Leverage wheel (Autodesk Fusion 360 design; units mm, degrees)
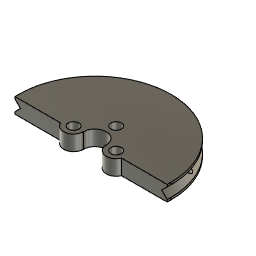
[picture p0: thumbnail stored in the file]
sketch "Sketch1" plane through (0, 0, 0) normal (0, 0, 1) x axis (1, 0, 0)
  line L1 (11.5, 12.5) -> (4.5, 12.5)
  line L2 (36.5, 12.5) -> (-13.5, 12.5)
  circle C1 centre (11.5, 19.5) radius 1.75
  circle C2 centre (18.5, 12.5) radius 1.75
  circle C3 centre (11.5, 5.5) radius 1.75
  circle C4 centre (11.5, 12.5) radius 3.75
  circle C5 centre (4.5, 12.5) radius 1.75
  circle C6 centre (11.5, 12.5) radius 25
  circle C7 centre (4.5, 12.5) radius 3.25
  circle C8 centre (18.5, 12.5) radius 3.25
  point P4 (4.5, 12.5)
  point P3 (4.5, 12.5)
  point P5 (11.5, 12.5)
  point P6 (11.5, 12.5)
  point P10 (-13.5, 12.5)
  point P11 (36.5, 12.5)
  coincident P4 L2
  coincident P3 P4
  parallel L1 L2
  coincident P5 P6
  concentric C4 C6
  coincident C6 P10
  coincident C6 P11
  concentric C5 C7
  tangent C4 C7
  concentric C2 C8
  tangent C4 C8
  dimension "d4" diameter C5 = 3.5
  dimension "d5" distance P3 P6 = 7
  dimension "d6" diameter C4 = 7.5
  dimension "d9" diameter C6 = 50
  dimension "d2" C-Pattern1-Angle = 360
extrude "Extrude1" new body sketch "Sketch1" profile of C1 C2 L1 L2 C4 C5 C6 C7 C8 along normal blind 5
sketch "Sketch4" plane through (0, 0, 5) normal (0, 0, 1) x axis (-1, 0, 0)
  line L1 (-36.5, -12.5) -> (-21.75, -12.5)
  line L2 (-1.25, -12.5) -> (13.5, -12.5)
  line L3 (13.5, -12.5) -> (-11.5, -12.5)
  line L4 (13.5, -13.75) -> (13.5, -12.5)
  line L5 (-11.5, -13.75) -> (13.5, -13.75)
  line L6 (-11.5, -12.5) -> (-11.5, -13.75)
  line L7 (-11.5, -11.25) -> (13.5, -11.25)
  line L8 (-1.25, -12.5) -> (13.5, -12.5)
  line L9 (13.5, -12.5) -> (-11.5, -12.5)
  line L10 (-11.5, -12.5) -> (-11.5, -11.25)
  line L11 (13.5, -11.25) -> (13.5, -12.5)
  line L12 (6.1777, 5.1777) -> (-11.5, -12.5)
  line L13 (-12.3839, -11.6161) -> (5.2938, 6.0616)
  line L14 (5.2938, 6.0616) -> (6.1777, 5.1777)
  line L15 (6.1777, 5.1777) -> (-11.5, -12.5)
  line L16 (-11.5, -12.5) -> (-10.6161, -13.3839)
  line L17 (-4.2522, -5.2522) -> (6.1777, 5.1777)
  line L18 (-10.6161, -13.3839) -> (7.0616, 4.2938)
  line L19 (7.0616, 4.2938) -> (6.1777, 5.1777)
  line L20 (-4.2522, -5.2522) -> (6.1777, 5.1777)
  line L21 (-11.5, -12.5) -> (-12.3839, -11.6161)
  line L22 (-11.5, 12.5) -> (-11.5, -12.5)
  line L23 (-12.75, -12.5) -> (-12.75, 12.5)
  line L24 (-12.75, 12.5) -> (-11.5, 12.5)
  line L25 (-11.5, 12.5) -> (-11.5, -12.5)
  line L26 (-11.5, -12.5) -> (-10.25, -12.5)
  line L27 (-11.5, -2.25) -> (-11.5, 12.5)
  line L28 (-10.25, -12.5) -> (-10.25, 12.5)
  line L29 (-10.25, 12.5) -> (-11.5, 12.5)
  line L30 (-11.5, -2.25) -> (-11.5, 12.5)
  line L31 (-11.5, -12.5) -> (-12.75, -12.5)
  line L32 (-29.1777, 5.1777) -> (-11.5, -12.5)
  line L33 (-12.3839, -13.3839) -> (-30.0616, 4.2938)
  line L34 (-30.0616, 4.2938) -> (-29.1777, 5.1777)
  line L35 (-29.1777, 5.1777) -> (-11.5, -12.5)
  line L36 (-11.5, -12.5) -> (-10.6161, -11.6161)
  line L37 (-18.7478, -5.2522) -> (-29.1777, 5.1777)
  line L38 (-10.6161, -11.6161) -> (-28.2938, 6.0616)
  line L39 (-28.2938, 6.0616) -> (-29.1777, 5.1777)
  line L40 (-18.7478, -5.2522) -> (-29.1777, 5.1777)
  line L41 (-11.5, -12.5) -> (-12.3839, -13.3839)
  line L42 (-36.5, -12.5) -> (-11.5, -12.5)
  line L43 (-11.5, -13.75) -> (-36.5, -13.75)
  line L44 (-36.5, -13.75) -> (-36.5, -12.5)
  line L45 (-36.5, -12.5) -> (-11.5, -12.5)
  line L46 (-11.5, -12.5) -> (-11.5, -11.25)
  line L47 (-21.75, -12.5) -> (-36.5, -12.5)
  line L48 (-11.5, -11.25) -> (-36.5, -11.25)
  line L49 (-36.5, -11.25) -> (-36.5, -12.5)
  line L50 (-21.75, -12.5) -> (-36.5, -12.5)
  line L51 (-11.5, -12.5) -> (-11.5, -13.75)
  line L52 (-29.1777, -30.1777) -> (-11.5, -12.5)
  line L53 (-10.6161, -13.3839) -> (-28.2938, -31.0616)
  line L54 (-28.2938, -31.0616) -> (-29.1777, -30.1777)
  line L55 (-29.1777, -30.1777) -> (-11.5, -12.5)
  line L56 (-11.5, -12.5) -> (-12.3839, -11.6161)
  line L57 (-18.7478, -19.7478) -> (-29.1777, -30.1777)
  line L58 (-12.3839, -11.6161) -> (-30.0616, -29.2938)
  line L59 (-30.0616, -29.2938) -> (-29.1777, -30.1777)
  line L60 (-18.7478, -19.7478) -> (-29.1777, -30.1777)
  line L61 (-11.5, -12.5) -> (-10.6161, -13.3839)
  line L62 (-11.5, -37.5) -> (-11.5, -12.5)
  line L63 (-10.25, -12.5) -> (-10.25, -37.5)
  line L64 (-10.25, -37.5) -> (-11.5, -37.5)
  line L65 (-11.5, -37.5) -> (-11.5, -12.5)
  line L66 (-11.5, -12.5) -> (-12.75, -12.5)
  line L67 (-11.5, -22.75) -> (-11.5, -37.5)
  line L68 (-12.75, -12.5) -> (-12.75, -37.5)
  line L69 (-12.75, -37.5) -> (-11.5, -37.5)
  line L70 (-11.5, -22.75) -> (-11.5, -37.5)
  line L71 (-11.5, -12.5) -> (-10.25, -12.5)
  line L72 (6.1777, -30.1777) -> (-11.5, -12.5)
  line L73 (-10.6161, -11.6161) -> (7.0616, -29.2938)
  line L74 (7.0616, -29.2938) -> (6.1777, -30.1777)
  line L75 (6.1777, -30.1777) -> (-11.5, -12.5)
  line L76 (-11.5, -12.5) -> (-12.3839, -13.3839)
  line L77 (-4.2522, -19.7478) -> (6.1777, -30.1777)
  line L78 (-12.3839, -13.3839) -> (5.2938, -31.0616)
  line L79 (5.2938, -31.0616) -> (6.1777, -30.1777)
  line L80 (-4.2522, -19.7478) -> (6.1777, -30.1777)
  line L81 (-11.5, -12.5) -> (-10.6161, -11.6161)
  circle C1 centre (-18.5, -12.5) radius 1.75
  circle C2 centre (-11.5, -19.5) radius 1.75
  circle C3 centre (-4.5, -12.5) radius 1.75
  arc A1 centre (-18.5, -12.5) radius 3.25 clockwise from (-21.75, -12.5) to (-15.25, -12.5)
  arc A2 centre (-11.5, -12.5) radius 25 clockwise from (13.5, -12.5) to (-36.5, -12.5)
  arc A3 centre (-4.5, -12.5) radius 3.25 clockwise from (-7.75, -12.5) to (-1.25, -12.5)
  arc A4 centre (-11.5, -12.5) radius 3.75 clockwise from (-7.75, -12.5) to (-15.25, -12.5)
  circle C4 centre (-11.5, -12.5) radius 22.5
  circle C5 centre (-4.5, -12.5) radius 3.25
  circle C6 centre (-11.5, -19.5) radius 3.25
  circle C7 centre (-18.5, -12.5) radius 3.25
  circle C8 centre (-11.5, -12.5) radius 6.25
  point P6 (-21.75, -12.5)
  point P9 (-11.5, -12.5)
  point P16 (-11.5, -12.5)
  point P4 (-4.5, -12.5)
  point P26 (-4.5, -12.5)
  point P8 (13.5, -12.5)
  point P22 (13.5, -12.5)
  point P23 (-11.5, -12.5)
  point P10 (-1.25, -12.5)
  point P27 (-1.25, -12.5)
  point P11 (-7.75, -12.5)
  point P24 (-7.75, -12.5)
  point P12 (-11.5, -12.5)
  point P20 (-11.5, -12.5)
  point P13 (-4.5, -12.5)
  point P28 (-4.5, -12.5)
  point P21 (-11.5, -12.5)
  point P17 (13.5, -12.5)
  point P25 (13.5, -12.5)
  point P18 (13.5, -13.75)
  point P29 (13.5, -11.25)
  point P19 (-11.5, -13.75)
  point P30 (-11.5, -11.25)
  point P44 (-11.5, -12.5)
  point P185 (-11.5, -12.5)
  concentric A2 C4
  concentric C3 C5
  concentric C2 C6
  tangent A4 C6
  concentric C1 C7
  coincident P6 C7
  horizontal L3
  vertical L4
  horizontal L5
  vertical L6
  coincident P9 P16
  symmetric P4 L3 P26
  symmetric P8 L3 P22
  symmetric P9 L3 P23
  symmetric P10 L3 P27
  symmetric P11 L3 P24
  symmetric P12 L3 P20
  symmetric P13 L3 P28
  symmetric P16 L3 P21
  symmetric P17 L3 P25
  symmetric P18 L3 P29
  symmetric P19 L3 P30
  coincident P44 P185
  dimension "d23" diameter C4 = 45
  dimension "d24" distance P16 P17 = 25
  dimension "d25" distance P16 P19 = 1.25
  dimension "d28" diameter C8 = 12.5
  dimension "d27" C-Pattern1-Angle = 360
sketch "Sketch5" plane through (0, 0, 5) normal (0, 0, 1) x axis (-1, 0, 0)
  line L1 (-36.5, -12.5) -> (-21.75, -12.5)
  line L2 (-1.25, -12.5) -> (13.5, -12.5)
  line L3 (-36.5, -11.25) -> (-36.5, -12.5)
  line L4 (-11.5, -11.25) -> (-36.5, -11.25)
  line L5 (13.5, -11.25) -> (13.5, -12.5)
  line L6 (-11.5, -11.25) -> (13.5, -11.25)
  circle C1 centre (-18.5, -12.5) radius 1.75
  circle C2 centre (-11.5, -19.5) radius 1.75
  circle C3 centre (-4.5, -12.5) radius 1.75
  arc A1 centre (-18.5, -12.5) radius 3.25 clockwise from (-21.75, -12.5) to (-15.25, -12.5)
  arc A2 centre (-11.5, -12.5) radius 25 clockwise from (13.5, -12.5) to (-36.5, -12.5)
  arc A3 centre (-4.5, -12.5) radius 3.25 clockwise from (-7.75, -12.5) to (-1.25, -12.5)
  arc A4 centre (-11.5, -12.5) radius 3.75 clockwise from (-7.75, -12.5) to (-15.25, -12.5)
extrude "Extrude5" add sketch "Sketch4" + "Sketch5" profile of S1:A1 S1:L1 S1:C4 S1:C7 S1:L42 S1:L45 S1:L47 S1:L48 S1:L50 S2:A1 S2:L1 S2:L2 S2:A3 S2:L3 S2:L4 S2:L5 S2:L6 to an object
move "Move1"
work_plane "WorkPlane1" AlongDistance -25
sketch "Sketch7" plane through (-25, 0, 0) normal (1, 0, 0) x axis (0, 1, 0)
  line L1 (-1.25, 0) -> (0, 0)
  line L2 (-1.25, 5) -> (-1.25, 0)
  line L3 (0, 5) -> (-1.25, 5)
  line L4 (0, 0) -> (0, 5)
  line L5 (0, 0) -> (25, 0)
  line L6 (0, 5) -> (0, 0)
  line L7 (0, 5) -> (25, 5)
  line L8 (0, 0) -> (0, 5)
  line L9 (3, 2.5) -> (-1.25, 2.5)
  circle C1 centre (0.95, 2.5) radius 1.1
  point P10 (-1.25, 2.5)
  point P12 (0.95, 2.5)
  midpoint L2 P10
  perpendicular L2 L9
  coincident L9 P12
  dimension "d39" diameter C1 = 2.2
  dimension "d40" distance L2 P12 = 2.2 (= "d39")
extrude "Extrude7" cut sketch "Sketch7" profile of C1 along normal blind 6
circular_pattern "C-Pattern2" TotalAngle 360
sketch "Sketch9" plane through (0, 0, 0) normal (0, 1, 0) x axis (1, 0, 0)
  line L1 (25, 0) -> (10, 0)
  line L2 (25, -5) -> (25, 0)
  line L3 (10, -5) -> (25, -5)
  line L4 (10, 0) -> (10, -5)
  line L5 (20.5, -2.5) -> (25, -2.5)
  line L6 (22.5, -2.5) -> (25, -5)
  line L7 (28.5355, -5) -> (25, -5)
  line L8 (25, 0) -> (22.5, -2.5)
  line L9 (23.2071, -2.5) -> (25.7071, -5)
  line L10 (25.7071, 0) -> (23.2071, -2.5)
  line L11 (24.5, -3.7929) -> (24.5, -1.2071)
  line L12 (25.7071, 0) -> (25.7071, -5)
  point P6 (25, -2.5)
  point P4 (25, -5)
  point P8 (25, -5)
  point P9 (22.5, -2.5)
  point P11 (24.5, -3.7929)
  point P13 (24.5, -1.2071)
  midpoint L2 P6
  perpendicular L2 L5
  horizontal L7
  coincident P4 P8
  coincident L5 P9
  perpendicular L6 L8
  coincident P8 L6
  coincident P11 L9
  coincident P13 L10
  dimension "d48" angle L6 L7 = 135
revolve "Revolve2" sketch "Sketch9" AlongAngle 360
sketch "Sketch8" plane through (0, -1.25, 0) normal (0, -1, 0) x axis (1, 0, 0)
  line L1 (-10, 0) -> (-25, 0)
  line L2 (-10, 5) -> (-10, 0)
  line L3 (-25, 5) -> (-10, 5)
  line L4 (-25, 0) -> (-25, 5)
  line L5 (-19.3392, 2.5) -> (-25, 2.5)
  line L6 (-22.5, 2.5) -> (-25, 5)
  line L7 (-21.4645, 5) -> (-25, 5)
  line L8 (-25, 0) -> (-22.5, 2.5)
  line L9 (-25, 5) -> (-25, 0)
  line L10 (-23.5607, 2.5) -> (-25.5303, 4.4697)
  line L11 (-25.5303, 0.5303) -> (-23.5607, 2.5)
  line L12 (-25.5303, 0.5303) -> (-25.5303, 4.4697)
  point P6 (-25, 2.5)
  point P5 (-25, 5)
  point P8 (-25, 5)
  point P9 (-22.5, 2.5)
  point P2 (-25, 0)
  point P11 (-25, 0)
  point P12 (-25, 0)
  point P13 (-25, 5)
  midpoint L4 P6
  perpendicular L4 L5
  horizontal L7
  coincident P5 P8
  coincident L5 P9
  coincident P2 P11
  coincident P2 P12
  coincident P5 P13
  dimension "d45" angle L6 L7 = 45
  dimension "d46" = 0.75
revolve "Revolve1" sketch "Sketch8" AlongAngle 360
extrude "Extrude6" cut sketch "Sketch7" along normal blind 2
circular_pattern "C-Pattern1" TotalAngle 360
sketch "Sketch2" plane through (0, 0, 2.5) normal (0, 0, 1) x axis (-1, 0, 0)
  line L1 (-36.5, -12.5) -> (-21.75, -12.5)
  line L2 (-1.25, -12.5) -> (13.5, -12.5)
  line L3 (18.5, -12.5) -> (-11.5, -12.5)
  line L4 (18.5, -15) -> (18.5, -12.5)
  line L5 (-11.5, -15) -> (18.5, -15)
  line L6 (-11.5, -12.5) -> (-11.5, -15)
  line L7 (-11.5, -12.5) -> (-9.7322, -14.2678)
  line L8 (-4.2522, -5.2522) -> (6.1777, 5.1777)
  line L9 (-9.7322, -14.2678) -> (11.481, 6.9454)
  line L10 (11.481, 6.9454) -> (9.7132, 8.7132)
  line L11 (9.7132, 8.7132) -> (-11.5, -12.5)
  line L12 (-11.5, -12.5) -> (-9, -12.5)
  line L13 (-11.5, -2.25) -> (-11.5, 12.5)
  line L14 (-9, -12.5) -> (-9, 17.5)
  line L15 (-9, 17.5) -> (-11.5, 17.5)
  line L16 (-11.5, 17.5) -> (-11.5, -12.5)
  line L17 (-11.5, -12.5) -> (-9.7322, -10.7322)
  line L18 (-18.7478, -5.2522) -> (-29.1777, 5.1777)
  line L19 (-9.7322, -10.7322) -> (-30.9454, 10.481)
  line L20 (-30.9454, 10.481) -> (-32.7132, 8.7132)
  line L21 (-32.7132, 8.7132) -> (-11.5, -12.5)
  line L22 (-11.5, -12.5) -> (-11.5, -10)
  line L23 (-21.75, -12.5) -> (-36.5, -12.5)
  line L24 (-11.5, -10) -> (-41.5, -10)
  line L25 (-41.5, -10) -> (-41.5, -12.5)
  line L26 (-41.5, -12.5) -> (-11.5, -12.5)
  line L27 (-11.5, -12.5) -> (-13.2678, -10.7322)
  line L28 (-18.7478, -19.7478) -> (-29.1777, -30.1777)
  line L29 (-13.2678, -10.7322) -> (-34.481, -31.9454)
  line L30 (-34.481, -31.9454) -> (-32.7132, -33.7132)
  line L31 (-32.7132, -33.7132) -> (-11.5, -12.5)
  line L32 (-11.5, -12.5) -> (-14, -12.5)
  line L33 (-11.5, -22.75) -> (-11.5, -37.5)
  line L34 (-14, -12.5) -> (-14, -42.5)
  line L35 (-14, -42.5) -> (-11.5, -42.5)
  line L36 (-11.5, -42.5) -> (-11.5, -12.5)
  line L37 (-11.5, -12.5) -> (-13.2678, -14.2678)
  line L38 (-4.2522, -19.7478) -> (6.1777, -30.1777)
  line L39 (-13.2678, -14.2678) -> (7.9454, -35.481)
  line L40 (7.9454, -35.481) -> (9.7132, -33.7132)
  line L41 (9.7132, -33.7132) -> (-11.5, -12.5)
  circle C1 centre (-18.5, -12.5) radius 1.75
  circle C2 centre (-11.5, -19.5) radius 1.75
  circle C3 centre (-4.5, -12.5) radius 1.75
  arc A1 centre (-18.5, -12.5) radius 3.25 clockwise from (-21.75, -12.5) to (-15.25, -12.5)
  arc A2 centre (-11.5, -12.5) radius 25 clockwise from (13.5, -12.5) to (-36.5, -12.5)
  arc A3 centre (-4.5, -12.5) radius 3.25 clockwise from (-7.75, -12.5) to (-1.25, -12.5)
  arc A4 centre (-11.5, -12.5) radius 3.75 clockwise from (-7.75, -12.5) to (-15.25, -12.5)
  circle C4 centre (-11.5, -12.5) radius 10.25
  circle C5 centre (-11.5, -12.5) radius 12.75
  point P10 (-1.25, -12.5)
  point P13 (-11.5, -12.5)
  point P14 (-11.5, -12.5)
  point P15 (18.5, -12.5)
  point P17 (-11.5, -15)
  concentric A2 C4
  coincident P10 C4
  concentric A2 C5
  horizontal L3
  vertical L4
  horizontal L5
  vertical L6
  coincident P13 P14
  dimension "d13" diameter C5 = 25.5
  dimension "d14" distance P14 P15 = 30
  dimension "d15" distance P14 P17 = 2.5
  dimension "d17" C-Pattern1-Angle = 360
extrude "Extrude2" add sketch "Sketch2" profile of A2 L3 L4 L5 L29 L30 L31 L34 L35 L36 L39 L40 L41 to an object
sketch "Sketch3" plane through (0, 0, 2.5) normal (0, 0, 1) x axis (-1, 0, 0)
  line L1 (-36.5, -12.5) -> (-21.75, -12.5)
  line L2 (-34.481, -31.9454) -> (-30.8568, -28.3213)
  line L3 (-32.7132, -33.7132) -> (-34.481, -31.9454)
  line L4 (-29.1777, -30.1777) -> (-32.7132, -33.7132)
  line L5 (-14, -42.5) -> (-14, -37.3747)
  line L6 (-11.5, -42.5) -> (-14, -42.5)
  line L7 (-11.5, -37.5) -> (-11.5, -42.5)
  line L8 (7.9454, -35.481) -> (4.3213, -31.8568)
  line L9 (9.7132, -33.7132) -> (7.9454, -35.481)
  line L10 (6.1777, -30.1777) -> (9.7132, -33.7132)
  line L11 (18.5, -15) -> (13.3747, -15)
  line L12 (18.5, -12.5) -> (18.5, -15)
  line L13 (-1.25, -12.5) -> (18.5, -12.5)
  line L14 (-11.5, -15) -> (18.5, -15)
  line L15 (18.5, -12.5) -> (-11.5, -12.5)
  line L16 (-4.2522, -19.7478) -> (6.1777, -30.1777)
  line L17 (-13.2678, -14.2678) -> (7.9454, -35.481)
  line L18 (-11.5, -42.5) -> (-11.5, -12.5)
  line L19 (-14, -12.5) -> (-14, -42.5)
  line L20 (-32.7132, -33.7132) -> (-11.5, -12.5)
  line L21 (-13.2678, -10.7322) -> (-34.481, -31.9454)
  circle C1 centre (-18.5, -12.5) radius 1.75
  circle C2 centre (-11.5, -19.5) radius 1.75
  circle C3 centre (-4.5, -12.5) radius 1.75
  arc A1 centre (-18.5, -12.5) radius 3.25 clockwise from (-21.75, -12.5) to (-15.25, -12.5)
  arc A2 centre (-11.5, -12.5) radius 25 clockwise from (-30.8568, -28.3213) to (-36.5, -12.5)
  arc A3 centre (-11.5, -12.5) radius 25 clockwise from (-14, -37.3747) to (-29.1777, -30.1777)
  arc A4 centre (-11.5, -12.5) radius 25 clockwise from (4.3213, -31.8568) to (-11.5, -37.5)
  arc A5 centre (-11.5, -12.5) radius 25 clockwise from (13.3747, -15) to (6.1777, -30.1777)
  arc A6 centre (-4.5, -12.5) radius 3.25 clockwise from (-7.75, -12.5) to (-1.25, -12.5)
  arc A7 centre (-11.5, -12.5) radius 3.75 clockwise from (-7.75, -12.5) to (-15.25, -12.5)
  circle C4 centre (-11.5, -12.5) radius 12.75
  circle C5 centre (-11.5, -12.5) radius 10.25
  circle C6 centre (-11.5, -12.5) radius 22.5
  concentric C5 C6
  dimension "d20" diameter C6 = 45
extrude "Extrude3" cut sketch "Sketch2" + "Sketch3" profile of S1:L1 S1:A2 S1:C5 S1:L23 S1:L26 S1:L29 S1:L34 S2:C4 S2:L14 S2:L16 S2:L17 S2:L18 S2:L19 S2:L20 S2:C6 to an object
